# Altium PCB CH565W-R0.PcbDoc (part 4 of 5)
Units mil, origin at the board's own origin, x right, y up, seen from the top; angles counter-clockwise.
Board outline 3947.04 x 3947.04 mil, 4 copper layers (Top Layer, Layer 1, Layer 2, Bottom Layer), stack 23.756 mil thick; 204 components, 168 nets, 932 pads, 1005 vias.
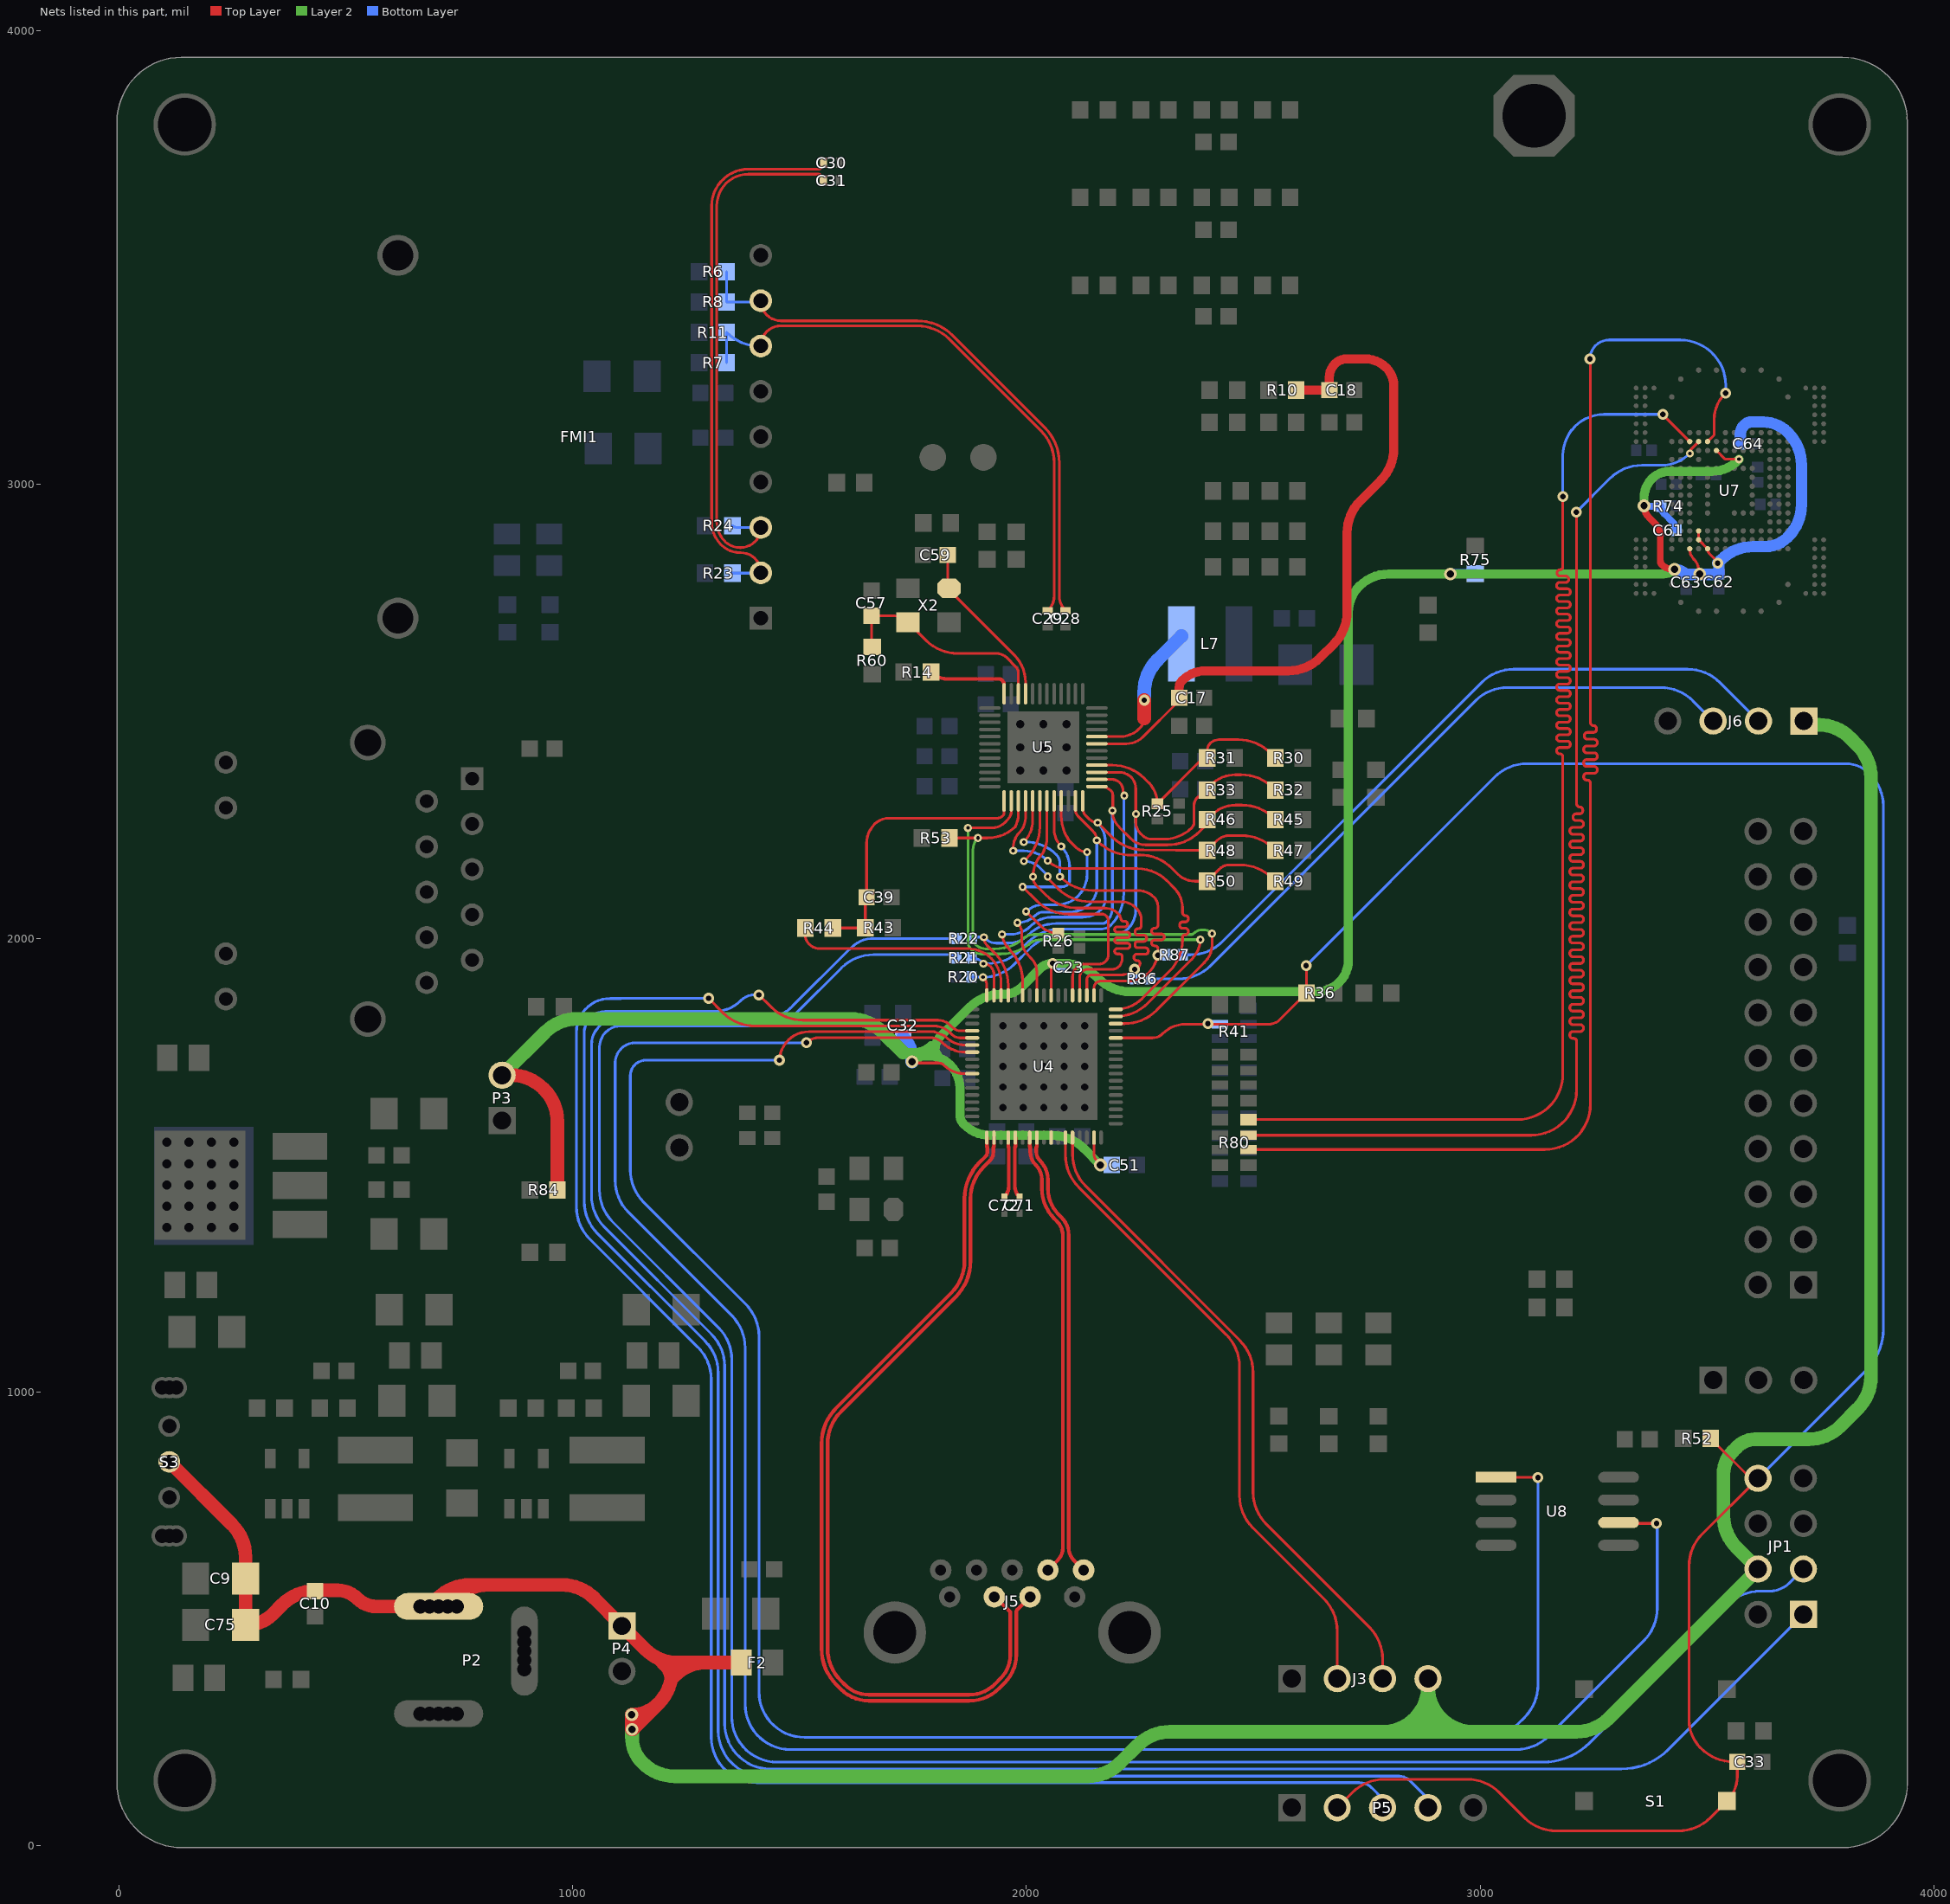
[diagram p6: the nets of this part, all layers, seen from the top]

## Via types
v1: diameter 17.72, hole 7.87, Top Layer to Bottom Layer, 556 vias
v2: diameter 24, hole 12, Top Layer to Bottom Layer, 366 vias
v3: diameter 28, hole 16, Top Layer to Bottom Layer, 63 vias
v4: diameter 17.72, hole 7.87, Top Layer to Bottom Layer, tented both sides, 8 vias
v5: diameter 24, hole 12, Top Layer to Bottom Layer, tented both sides, 5 vias
v6: diameter 26, hole 14, Top Layer to Bottom Layer, 2 vias
v7: diameter 19.68, hole 10, Top Layer to Bottom Layer, 1 vias
v8: diameter 20, hole 10, Top Layer to Bottom Layer, 1 vias
v9: diameter 28, hole 16, Top Layer to Bottom Layer, tented both sides, 1 vias
v10: diameter 32, hole 18, Top Layer to Bottom Layer, 1 vias
v11: diameter 17.72, hole 12, Top Layer to Bottom Layer, 1 vias

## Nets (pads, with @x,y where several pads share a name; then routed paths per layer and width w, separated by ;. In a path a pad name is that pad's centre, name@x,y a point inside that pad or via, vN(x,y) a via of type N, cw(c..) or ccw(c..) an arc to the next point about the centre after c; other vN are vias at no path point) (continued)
NetR80_6: R80.6 U7.J5 | length 3153.7
  Top Layer w6: R80.6@2489.51,1533.95 3143.25,1533.95 ccw(c3143.25,1633.95) 3243.25,1633.95 3243.25,2338.86 3243.25,2341.86 ccw(c3236.5,2341.86) 3236.5,2348.61 3235,2348.61 cw(c3235,2355.36) 3228.25,2355.36 3228.25,2356.86 cw(c3235,2356.86) 3235,2363.61 3251.5,2363.61 ccw(c3251.5,2370.36) 3258.25,2370.36 3258.25,2371.86 ccw(c3251.5,2371.86) 3251.5,2378.61 3235,2378.61 cw(c3235,2385.36) 3228.25,2385.36 3228.25,2386.86 cw(c3235,2386.86) 3235,2393.61 3251.5,2393.61 ccw(c3251.5,2400.36) 3258.25,2400.36 3258.25,2401.86 ccw(c3251.5,2401.86) 3251.5,2408.61 3235,2408.61 cw(c3235,2415.36) 3228.25,2415.36 3228.25,2416.86 cw(c3235,2416.86) 3235,2423.61 3251.5,2423.61 ccw(c3251.5,2430.36) 3258.25,2430.36 3258.25,2431.86 ccw(c3251.5,2431.86) 3251.5,2438.61 3236.56,2438.61 cw(c3236.56,2445.36) 3229.81,2445.36 3229.81,2446.86 cw(c3236.56,2446.86) 3236.56,2453.61 3250,2453.61 ccw(c3250,2460.36) 3256.75,2460.36 3256.75,2461.86 ccw(c3250,2461.86) 3250,2468.61 cw(c3250,2475.36) 3243.25,2475.36 3243.25,2543.86 3243.25,3275.62 ccw(c3242.12,3275.62) v2(3242.12,3276.76) ; U7.J5@3501.47,3094.85 3515.93,3109.33 3515.93,3143.38 cw(c3594.92,3143.38) 3539.07,3199.23 v2(3541.48,3201.64)
  Bottom Layer w6: v2(3242.12,3276.76) cw(c3284.22,3276.76) 3284.22,3318.85 3441.48,3318.85 cw(c3441.48,3218.85) 3541.48,3218.85 v2(3541.48,3201.64)
NetR80_7: R80.7 U7.J4 | length 3184.2
  Top Layer w6: R80.7@2489.51,1565.45 3112.82,1565.45 ccw(c3112.82,1665.45) 3212.82,1665.44 3212.82,1769.53 3212.82,1772.53 ccw(c3206.07,1772.53) 3206.07,1779.28 3204.57,1779.28 cw(c3204.57,1786.03) 3197.82,1786.03 3197.82,1787.53 cw(c3204.57,1787.53) 3204.57,1794.28 3221.07,1794.28 ccw(c3221.07,1801.03) 3227.82,1801.03 3227.82,1802.53 ccw(c3221.07,1802.53) 3221.07,1809.28 3204.57,1809.28 cw(c3204.57,1816.03) 3197.82,1816.03 3197.82,1817.53 cw(c3204.57,1817.53) 3204.57,1824.28 3221.07,1824.28 ccw(c3221.07,1831.03) 3227.82,1831.03 3227.82,1832.53 ccw(c3221.07,1832.53) 3221.07,1839.28 3204.57,1839.28 cw(c3204.57,1846.03) 3197.82,1846.03 3197.82,1847.53 cw(c3204.57,1847.53) 3204.57,1854.28 3221.07,1854.28 ccw(c3221.07,1861.03) 3227.82,1861.03 3227.82,1862.53 ccw(c3221.07,1862.53) 3221.07,1869.28 3204.57,1869.28 cw(c3204.57,1876.03) 3197.82,1876.03 3197.82,1877.53 cw(c3204.57,1877.53) 3204.57,1884.28 3221.07,1884.28 ccw(c3221.07,1891.03) 3227.82,1891.03 3227.82,1892.53 ccw(c3221.07,1892.53) 3221.07,1899.28 3204.57,1899.28 cw(c3204.57,1906.03) 3197.82,1906.03 3197.82,1907.53 cw(c3204.57,1907.53) 3204.57,1914.28 3221.07,1914.28 ccw(c3221.07,1921.03) 3227.82,1921.03 3227.82,1922.53 ccw(c3221.07,1922.53) 3221.07,1929.28 3204.57,1929.28 cw(c3204.57,1936.03) 3197.82,1936.03 3197.82,1937.53 cw(c3204.57,1937.53) 3204.57,1944.28 3221.07,1944.28 ccw(c3221.07,1951.03) 3227.82,1951.03 3227.82,1952.53 ccw(c3221.07,1952.53) 3221.07,1959.28 3204.57,1959.28 cw(c3204.57,1966.03) 3197.82,1966.03 3197.82,1967.53 cw(c3204.57,1967.53) 3204.57,1974.28 3221.07,1974.28 ccw(c3221.07,1981.03) 3227.82,1981.03 3227.82,1982.53 ccw(c3221.07,1982.53) 3221.07,1989.28 3204.57,1989.28 cw(c3204.57,1996.03) 3197.82,1996.03 3197.82,1997.53 cw(c3204.57,1997.53) 3204.57,2004.28 3221.07,2004.28 ccw(c3221.07,2011.03) 3227.82,2011.03 3227.82,2012.53 ccw(c3221.07,2012.53) 3221.07,2019.28 3204.57,2019.28 cw(c3204.57,2026.03) 3197.82,2026.03 3197.82,2027.53 cw(c3204.57,2027.53) 3204.57,2034.28 3221.07,2034.28 ccw(c3221.07,2041.03) 3227.82,2041.03 3227.82,2042.53 ccw(c3221.07,2042.53) 3221.07,2049.28 3204.57,2049.28 cw(c3204.57,2056.03) 3197.82,2056.03 3197.82,2057.53 cw(c3204.57,2057.53) 3204.57,2064.28 3221.07,2064.28 ccw(c3221.07,2071.03) 3227.82,2071.03 3227.82,2072.53 ccw(c3221.07,2072.53) 3221.07,2079.28 3204.57,2079.28 cw(c3204.57,2086.03) 3197.82,2086.03 3197.82,2087.53 cw(c3204.57,2087.53) 3204.57,2094.28 3221.07,2094.28 ccw(c3221.07,2101.03) 3227.82,2101.03 3227.82,2102.53 ccw(c3221.07,2102.53) 3221.07,2109.28 3204.57,2109.28 cw(c3204.57,2116.03) 3197.82,2116.03 3197.82,2117.53 cw(c3204.57,2117.53) 3204.57,2124.28 3221.07,2124.28 ccw(c3221.07,2131.03) 3227.82,2131.03 3227.82,2132.53 ccw(c3221.07,2132.53) 3221.07,2139.28 3204.57,2139.28 cw(c3204.57,2146.03) 3197.82,2146.03 3197.82,2147.53 cw(c3204.57,2147.53) 3204.57,2154.28 3221.07,2154.28 ccw(c3221.07,2161.03) 3227.82,2161.03 3227.82,2162.53 ccw(c3221.07,2162.53) 3221.07,2169.28 3204.57,2169.28 cw(c3204.57,2176.03) 3197.82,2176.03 3197.82,2177.53 cw(c3204.57,2177.53) 3204.57,2184.28 3221.07,2184.28 ccw(c3221.07,2191.03) 3227.82,2191.03 3227.82,2192.53 ccw(c3221.07,2192.53) 3221.07,2199.28 3204.57,2199.28 cw(c3204.57,2206.03) 3197.82,2206.03 3197.82,2207.53 cw(c3204.57,2207.53) 3204.57,2214.28 3221.07,2214.28 ccw(c3221.07,2221.03) 3227.82,2221.03 3227.82,2222.53 ccw(c3221.07,2222.53) 3221.07,2229.28 3204.57,2229.28 cw(c3204.57,2236.03) 3197.82,2236.03 3197.82,2237.53 cw(c3204.57,2237.53) 3204.57,2244.28 3221.07,2244.28 ccw(c3221.07,2251.03) 3227.82,2251.03 3227.82,2252.53 ccw(c3221.07,2252.53) 3221.07,2259.28 3211.72,2259.28 cw(c3211.72,2266.03) 3204.97,2266.03 3204.97,2267.53 cw(c3211.72,2267.53) 3211.72,2274.28 3219.57,2274.28 ccw(c3219.57,2281.03) 3226.32,2281.03 3226.32,2282.53 ccw(c3219.57,2282.53) 3219.57,2289.28 cw(c3219.57,2296.03) 3212.82,2296.03 3212.82,2345.59 3212.82,2348.59 v2@3212.82,2939.27 ; v4(3462.46,3068.75) 3464.7,3070.99 3464.7,3077.76 U7.J4@3481.78,3094.85
  Bottom Layer w6: v2(3211.9,2939.27) 3285.85,3013.21 cw(c3356.56,2942.5) 3356.56,3042.5 3399.09,3042.5 ccw(c3399.09,3132.11) v4(3462.46,3068.75)
NetR80_8: R80.8 U7.J3 | length 3166.7
  Top Layer w6: R80.8@2489.51,1600.1 3082.41,1600.1 ccw(c3082.41,1700.1) 3182.41,1700.1 3182.41,2397 3182.41,2400 ccw(c3176.11,2400) 3176.11,2406.3 3175.12,2406.3 cw(c3175.12,2412.6) 3168.82,2412.6 3168.82,2414 cw(c3175.12,2414) 3175.12,2420.3 3192.52,2420.3 ccw(c3192.52,2426.6) 3198.82,2426.6 3198.82,2428 ccw(c3192.52,2428) 3192.52,2434.3 3175.12,2434.3 cw(c3175.12,2440.6) 3168.82,2440.6 3168.82,2442 cw(c3175.12,2442) 3175.12,2448.3 3192.52,2448.3 ccw(c3192.52,2454.6) 3198.82,2454.6 3198.82,2456 ccw(c3192.52,2456) 3192.52,2462.3 3175.12,2462.3 cw(c3175.12,2468.6) 3168.82,2468.6 3168.82,2470 cw(c3175.12,2470) 3175.12,2476.3 3192.52,2476.3 ccw(c3192.52,2482.6) 3198.82,2482.6 3198.82,2484 ccw(c3192.52,2484) 3192.52,2490.3 3175.12,2490.3 cw(c3175.12,2496.6) 3168.82,2496.6 3168.82,2498 cw(c3175.12,2498) 3175.12,2504.3 3192.52,2504.3 ccw(c3192.52,2510.6) 3198.82,2510.6 3198.82,2512 ccw(c3192.52,2512) 3192.52,2518.3 3175.12,2518.3 cw(c3175.12,2524.6) 3168.82,2524.6 3168.82,2526 cw(c3175.12,2526) 3175.12,2532.3 3192.52,2532.3 ccw(c3192.52,2538.6) 3198.82,2538.6 3198.82,2540 ccw(c3192.52,2540) 3192.52,2546.3 3175.12,2546.3 cw(c3175.12,2552.6) 3168.82,2552.6 3168.82,2554 cw(c3175.12,2554) 3175.12,2560.3 3192.52,2560.3 ccw(c3192.52,2566.6) 3198.82,2566.6 3198.82,2568 ccw(c3192.52,2568) 3192.52,2574.3 3175.12,2574.3 cw(c3175.12,2580.6) 3168.82,2580.6 3168.82,2582 cw(c3175.12,2582) 3175.12,2588.3 3192.52,2588.3 ccw(c3192.52,2594.6) 3198.82,2594.6 3198.82,2596 ccw(c3192.52,2596) 3192.52,2602.3 3175.12,2602.3 cw(c3175.12,2608.6) 3168.82,2608.6 3168.82,2610 cw(c3175.12,2610) 3175.12,2616.3 3192.52,2616.3 ccw(c3192.52,2622.6) 3198.82,2622.6 3198.82,2624 ccw(c3192.52,2624) 3192.52,2630.3 3175.12,2630.3 cw(c3175.12,2636.6) 3168.82,2636.6 3168.82,2638 cw(c3175.12,2638) 3175.12,2644.3 3192.52,2644.3 ccw(c3192.52,2650.6) 3198.82,2650.6 3198.82,2652 ccw(c3192.52,2652) 3192.52,2658.3 3175.12,2658.3 cw(c3175.12,2664.6) 3168.82,2664.6 3168.82,2666 cw(c3175.12,2666) 3175.12,2672.3 3192.52,2672.3 ccw(c3192.52,2678.6) 3198.82,2678.6 3198.82,2680 ccw(c3192.52,2680) 3192.52,2686.3 3175.12,2686.3 cw(c3175.12,2692.6) 3168.82,2692.6 3168.82,2694 cw(c3175.12,2694) 3175.12,2700.3 3192.52,2700.3 ccw(c3192.52,2706.6) 3198.82,2706.6 3198.82,2708 ccw(c3192.52,2708) 3192.52,2714.3 3175.12,2714.3 cw(c3175.12,2720.6) 3168.82,2720.6 3168.82,2722 cw(c3175.12,2722) 3175.12,2728.3 3192.52,2728.3 ccw(c3192.52,2734.6) 3198.82,2734.6 3198.82,2736 ccw(c3192.52,2736) 3192.52,2742.3 3175.12,2742.3 cw(c3175.12,2748.6) 3168.82,2748.6 3168.82,2750 cw(c3175.12,2750) 3175.12,2756.3 3192.52,2756.3 ccw(c3192.52,2762.6) 3198.82,2762.6 3198.82,2764 ccw(c3192.52,2764) 3192.52,2770.3 3175.12,2770.3 cw(c3175.12,2776.6) 3168.82,2776.6 3168.82,2778 cw(c3175.12,2778) 3175.12,2784.3 3188.9,2784.3 ccw(c3188.9,2790.6) 3195.2,2790.6 3195.2,2792 ccw(c3188.9,2792) 3188.9,2798.3 3176.11,2798.3 cw(c3176.11,2804.6) 3169.81,2804.6 3169.81,2806 cw(c3176.11,2806) 3176.11,2812.3 ccw(c3176.11,2818.6) 3182.41,2818.6 3182.41,2937.19 v2(3182.41,2973.49) ; v2(3402.8,3154.97) 3402.8,3154.16 U7.J3@3462.1,3094.85
  Bottom Layer w6: v2(3182.41,2973.49) 3182.41,3064.16 cw(c3273.22,3064.16) 3273.22,3154.97 v2(3402.8,3154.97)
PA19: U4.10
PB24: R44.2 U4.49 | length 535
  Top Layer w6: R44.2@1512.38,2022.43 1512.38,2007.08 ccw(c1540.98,2007.08) 1520.75,1986.86 ccw(c1544.85,2010.95) 1544.85,1976.88 1870.85,1976.88 cw(c1870.85,1904.71) 1921.89,1955.74 cw(c1868.24,1902.09) 1944.11,1902.09 U4.49@1944.11,1873.9
PHYRSTB: C39.2 R43.1 R44.1 U5.13 | length 621.3
  Top Layer w6: R44.1@1573.01,2022.43 1642.99,2022.43 ccw(c1642.99,2024.94) R43.1@1644.77,2023.17 1644.77,2083.54 cw(c1654.35,2083.54) C39.2@1647.57,2090.31 1647.57,2189.92 1647.57,2209.43 cw(c1706.65,2209.43) 1664.88,2251.21 cw(c1697.2,2218.88) 1697.2,2264.59 1745.25,2264.59 1935.08,2264.59 ccw(c1935.08,2282.62) 1947.83,2269.87 ccw(c1941.09,2276.61) 1950.62,2276.61 U5.13@1950.62,2297.13
PWR: C9.2 C10.2 C75.2 F2.2 J3.4 J6.1 JP1.4 P2.1 P4.1 S3.1 | length 7815.1
  Top Layer w30: S3.1@110.18,845.58 249.02,706.74 cw(c178.31,636.03) 278.31,636.03 C9.2@278.31,588.13 C75.2@278.31,486.14 282.16,486.14 ccw(c282.16,564.49) 337.56,509.09 359.63,531.15 cw(c430.34,460.44) 430.34,560.44 C10.2@431.73,560.44 ; C10.2@431.73,562.32 481.16,562.32 cw(c481.16,500.89) 524.6,544.33 ccw(c567.23,586.96) 567.23,526.67 P2.1@664.07,526.67 P2.1@684.07,526.67 ; P2.1@684.07,540.95 P2.1@684.07,526.67 ; P2.1@704.07,526.67 722.44,545.04 cw(c793.15,474.33) 793.15,574.33 ; P2.1@724.07,526.67 742.44,545.04 cw(c813.15,474.33) 813.15,574.33 ; 1187.97,311.98 1188.86,312.87 ccw(c1118.15,383.58) 1216.67,366.44 ; F2.2@1371.15,402.99 1294.64,402.99 ; P2.1@684.07,526.67 702.44,545.04 cw(c773.15,474.33) 773.15,574.33 793.15,574.33 ; 793.15,574.33 813.15,574.33 ; 813.15,574.33 976.1,574.33 cw(c976.1,474.33) 1046.81,545.04 P4.1@1108.22,483.63 1159.57,432.28 ccw(c1230.28,502.99) 1189.19,411.82 ; 1189.19,411.82 ccw(c1230.28,502.99) 1230.28,402.99 1237.56,402.99 ; 1189.19,411.82 1204.02,396.99 cw(c1173.47,366.44) 1216.67,366.44 ; 1216.67,366.44 ccw(c1118.15,383.58) 1218.15,383.58 cw(c1237.56,383.58) 1237.56,402.99 ; 1216.67,366.44 1223.93,373.7 cw(c1294.64,302.99) 1294.64,402.99 ; 1237.56,402.99 1294.64,402.99 ; v3(1129.84,287.9) ccw(c1129.84,370.1) 1187.94,311.95 1132.76,256.77 cw(c1130.21,259.32) v3(1130.21,255.71) 1130.21,287.54 v3(1129.84,287.9)
  Layer 2 w30: v3(1129.84,287.9) cw(c1126.07,284.13) 1131.41,284.13 1131.41,224.96 ; v3(1130.21,255.71) 1130.21,238.8 ccw(c1210.53,238.8) 1131.41,224.96 ; J3.4@2885.09,367.45 J3.4@2885.09,350.37 ; J6.1@3713.66,2478.72 3713.66,2470.27 3747,2470.27 cw(c3747,2373.81) 3815.2,2442.02 3832.46,2424.76 cw(c3761.75,2354.05) 3861.75,2354.05 3861.75,1033.06 cw(c3761.75,1033.06) 3832.46,962.35 3794.57,924.46 cw(c3723.86,995.17) 3723.86,895.17 3606.65,895.17 ccw(c3606.65,839.43) 3567.23,878.85 3557.83,869.44 ccw(c3608.84,818.44) 3536.7,818.44 3536.7,726.61 ccw(c3636.7,726.61) 3565.99,655.9 JP1.4@3612.66,609.23 3283.09,279.66 cw(c3212.38,350.37) 3212.38,250.37 2985.09,250.37 ; 1131.41,224.96 ccw(c1210.53,238.8) 1153.73,182 1154.11,181.62 ccw(c1224.82,252.33) 1224.82,152.33 2135.56,152.33 ccw(c2135.56,252.33) 2206.27,181.62 2245.73,221.08 cw(c2316.44,150.37) 2316.44,250.37 2785.09,250.37 ; 2785.09,250.37 ccw(c2785.09,350.37) J3.4@2885.09,350.37 ; 2785.09,250.37 2853.49,250.37 ; 2853.49,250.37 ccw(c2853.49,281.96) 2885.09,281.96 2885.09,299.15 ; 2853.49,250.37 2933.87,250.37 ; 2885.09,299.15 ccw(c2933.87,299.15) 2933.87,250.37 ; 2885.09,299.15 J3.4@2885.09,350.37 ; J3.4@2885.09,350.37 ccw(c2985.09,350.37) 2985.09,250.37 ; 2933.87,250.37 2985.09,250.37
REGOUT: L7.1 U5.32 | length 362
  Top Layer w6: U5.32@2155.35,2444.41 2206.47,2444.41 ccw(c2206.47,2504.19) 2248.74,2461.92 ccw(c2204.49,2506.17) 2267.07,2506.17 2267.07,2509.74
  Top Layer w30: 2259.69,2484.21 v2(2259.69,2524.71)
  Bottom Layer w30: v2(2259.69,2524.71) 2259.69,2542.66 cw(c2359.69,2542.66) 2288.98,2613.37 L7.1@2341.44,2665.83
RGMII_MDC: U4.33 U5.14 | length 1207.3
  Top Layer w6: v1(1871,2243) 1924.08,2243 1924.37,2243.29 ccw(c1924.37,2281.73) 1951.55,2254.55 ; 1951.56,2254.57 1959.29,2262.29 ; 1959.3,2262.3 ccw(c1942.19,2279.39) 1962.44,2266.18 ccw(c1942.19,2279.39) 1966.37,2279.39 U5.14@1966.37,2302.68 ; U4.33@2196.78,1827.36 ccw(c2196.78,1927) 2267.23,1856.54 2363.6,1952.91 ccw(c2314.1,2002.42) v1@2384.11,2002.42
  Layer 2 w6: v1(1871,2243) 1871,1993.43 ccw(c1899,1993.43) 1879.2,1973.63 ccw(c1899.3,1993.73) 1899.29,1965.3 1944,1965.3 ccw(c1944,2065.3) 2004.21,1985.46 ; v1(2383.28,1996.84) 2386.18,1993.94 ccw(c2379.17,1986.92) 2379.17,1996.84 2031.69,1996.84 ccw(c2031.69,1957.98) 2010.24,1990.39 ; 2004.21,1985.46 ccw(c1944,2065.3) 2010.24,1990.39 ; 2004.21,1985.46 cw(c2031.69,1957.98) 2010.24,1990.39
RGMII_MDIO: R53.2 U4.32 U5.15 | length 1306.6
  Top Layer w6: R53.2@1830.07,2220.81 1914.42,2220.81 ccw(c1914.42,2307.37) 1975.63,2246.16 ccw(c1920.26,2273.74) 1982.12,2273.74 U5.15@1982.12,2302.68 ; U4.32@2196.78,1811.61 2216.3,1811.61 ccw(c2216.3,1911.61) 2287.01,1840.9 2387.37,1941.26 ccw(c2316.66,2011.97) 2394.78,1949.54 ccw(c2360.44,1983.87) 2405.96,1966.95 ccw(c2360.44,1983.87) 2409,1983.87 v1(2409,2010)
  Layer 2 w6: v1(1893,2221) ccw(c1919.56,2194.44) 1882,2194.44 1882,2001.36 ccw(c1904.69,2001.36) 1888.64,1985.32 ccw(c1909.84,2006.52) 1909.84,1976.54 1930.17,1976.54 ccw(c1930.17,2076.54) 1996.78,2001.96 ; 1992.54,1998.37 cw(c2015.88,1975.03) 1996.78,2001.96 ; v1(2409,2010) ccw(c2386.59,1987.59) 2393.97,2018.41 2388.01,2018.41 ccw(c2388.01,1990.69) 2368.41,2010.29 cw(c2362.98,2015.73) 2362.98,2008.04 2015.88,2008.04 ccw(c2015.88,1975.03) 1996.78,2001.96
RGMII_RXC: R25.2 R30.2 R31.1 U5.28 | length 519.8
  Top Layer w6: U5.28@2155.35,2381.42 2189.52,2381.42 cw(c2189.52,2281.42) 2260.23,2352.13 2269.2,2343.16 cw(c2222.61,2296.57) R25.2@2288.5,2296.57 2383.21,2391.28 cw(c2398.43,2376.05) R31.1@2398.43,2397.59 2398.43,2413.55 cw(c2421.43,2413.55) 2405.17,2429.81 cw(c2424.04,2410.94) 2424.04,2437.62 2467.13,2437.62 cw(c2467.13,2337.62) 2537.84,2408.33 R30.2@2548.59,2397.59
RGMII_RXD0: R21.1 U4.50 U5.26 | length 795.6
  Top Layer w6: v1(1905.2,1943.91) cw(c1905.2,1921.68) 1920.92,1937.4 cw(c1902.98,1919.46) 1928.36,1919.46 U4.50@1928.36,1873.9 ; U5.26@2155.35,2349.93 2188.26,2349.93 cw(c2188.26,2324.79) 2206.04,2342.56 cw(c2190.38,2326.91) 2212.52,2326.91 v1@2212.52,2314.19
  Bottom Layer w6: R21.1@1878.52,1957.02 cw(c1878.52,1924.24) 1901.7,1947.42 v1(1905.2,1943.91) 1914.97,1943.91 ccw(c1914.97,2043.91) 1985.68,1973.2 2003.59,1991.11 cw(c2074.3,1920.4) 2074.3,2020.4 2166.88,2020.4 ccw(c2166.88,2046.35) 2185.23,2028 ccw(c2114.52,2098.71) 2214.52,2098.71 v1@2214.52,2314.19
  other v1: 2215.52,2314.19
RGMII_RXD1: R22.1 R45.2 R46.1 U4.48 U5.25 | length 1223.9
  Top Layer w6: v1(1905.97,2002.04) ccw(c1932.45,2002.04) 1913.73,1983.32 1930.56,1966.48 cw(c1859.85,1895.77) 1959.85,1895.77 U4.48@1959.85,1873.9 ; U5.25@2155.35,2334.18 2163.85,2334.18 cw(c2163.85,2301.73) 2186.8,2324.67 cw(c2178.22,2316.1) 2190.35,2316.1 v1@2190.35,2281.15 ; v1(2189.35,2281.15) ccw(c2240.43,2281.15) 2204.31,2245.04 2230.69,2218.67 ccw(c2262.13,2250.11) 2262.13,2205.64 2311.08,2205.64 ccw(c2311.08,2305.64) 2381.79,2234.93 2398.43,2251.58 cw(c2403.74,2251.58) R46.1@2399.98,2255.32 ; R46.1@2398.43,2261.58 2408.7,2271.85 cw(c2460.89,2219.66) 2460.89,2293.46 2475.28,2293.46 cw(c2475.28,2193.46) 2545.99,2264.17 R45.2@2548.59,2261.58 ; R45.2@2548.37,2251.79 R45.2@2548.59,2251.58
  Bottom Layer w6: R22.1@1879.11,1999.15 cw(c1887.36,1990.89) 1887.36,2002.57 1905.97,2002.57 1909.7,1998.84 ccw(c1933.3,2022.44) 1933.3,1989.06 1960.74,1989.06 ccw(c1960.74,2049.37) 2003.38,2006.73 cw(c2065.25,1944.86) 2065.25,2032.36 2167.01,2032.36 ccw(c2167.01,2046.23) 2176.81,2036.42 ccw(c2146.54,2066.69) 2189.35,2066.69 v1(2189.35,2281.15)
RGMII_RXD2: R47.2 R48.1 U4.46 U5.24 | length 1081
  Top Layer w6: v1(1946.21,2008.38) ccw(c2001.06,2014.78) 1962.02,1975.74 cw(c1957.77,1971.51) 1963.2,1974.06 cw(c1895.23,1906.1) 1991.35,1906.1 U4.46@1991.35,1873.9 ; U5.24@2123.85,2302.68 2123.85,2286.6 ccw(c2146.35,2286.6) 2125.74,2277.56 ccw(c2146.35,2286.6) 2130.44,2270.69 2138.9,2262.23 ccw(c2156.99,2280.32) v1(2156.99,2254.74) 2187.8,2223.93 ccw(c2258.51,2294.64) 2189.72,2222.06 ccw(c2258.51,2294.64) 2258.51,2194.64 cw(c2258.51,2188.64) 2258.6,2194.64 2398.43,2193.18 R48.1@2398.48,2193.17 ; R48.1@2398.43,2188.57 R48.1@2400.93,2191.07 ; R48.1@2398.43,2193.57 2419.69,2214.83 cw(c2447.24,2187.28) 2447.24,2226.24 2474.49,2226.24 cw(c2474.49,2126.24) 2545.2,2196.95 R47.2@2548.59,2193.57 ; R47.2@2548.45,2188.71 R47.2@2548.59,2188.57
  Bottom Layer w6: v1(1946.21,2008.38) 1963.48,2008.38 ccw(c1963.48,2075.18) 2010.71,2027.95 cw(c2054.88,1983.78) 2054.88,2046.24 2123.69,2046.24 ccw(c2123.69,2104.35) 2164.77,2063.26 ccw(c2143.93,2084.11) 2173.41,2084.11 2173.41,2215.1 ccw(c2117.35,2215.1) 2170.67,2232.4 ccw(c2117.35,2215.1) v1(2156.99,2254.74)
RGMII_RXD3: R49.2 R50.1 U4.44 U5.23 | length 1039.2
  Top Layer w6: v1(1980.11,2034.15) cw(c1956.73,2010.77) 1989.79,2010.77 1989.79,1994.93 ccw(c2034.68,1994.93) 2002.94,1963.18 2010.28,1955.84 ; 2010.31,1955.81 cw(c1979.95,1925.51) 2022.85,1925.51 U4.44@2022.85,1873.9 ; U5.23@2108.1,2302.68 2108.1,2283.07 ccw(c2128.79,2283.07) 2114.16,2268.45 2146.73,2235.88 cw(c2126.67,2215.82) 2155.04,2215.82 2158.5,2212.35 ccw(c2229.21,2283.06) 2216.03,2183.93 ccw(c2229.21,2283.06) 2229.21,2183.06 2249.83,2183.06 ; 2249.83,2183.67 cw(c2249.83,2083.67) 2320.54,2154.38 2333.88,2141.05 ccw(c2371.26,2178.44) 2371.26,2125.57 R50.1@2398.43,2125.57 ; R50.1@2399.78,2126.12 ccw(c2399.78,2124.22) R50.1@2398.43,2125.57 ; R49.2@2534.74,2127.17 cw(c2531.62,2122.04) R49.2@2535.79,2126.36 ; R49.2@2548.59,2125.57 2541.95,2132.2 ccw(c2471.24,2061.49) 2471.24,2161.49 2447.02,2161.49 ccw(c2447.02,2130.92) 2425.4,2152.54 R50.1@2398.43,2125.57
  Bottom Layer w6: v1(1980.11,2034.15) ccw(c1980.11,2091.39) 2020.58,2050.91 cw(c2036.32,2035.17) 2036.32,2057.43 2094.78,2057.43 ccw(c2094.78,2121.85) 2140.33,2076.3 ccw(c2104.82,2111.81) 2155.04,2111.81 v1(2155.04,2215.81)
RGMII_RXDV: R20.1 R32.2 R33.1 U4.51 U5.27 | length 1274.3
  Top Layer w6: v1(1904.17,1913.87) v1@1906.35,1911.69 ; v1@1906.36,1911.68 cw(c1891.23,1896.58) 1912.61,1896.58 U4.51@1912.61,1873.9 ; U5.27@2155.35,2365.67 2205.11,2365.67 cw(c2205.11,2330.04) 2230.31,2355.24 cw(c2204.41,2329.35) 2241.03,2329.35 2241.03,2255.21 ccw(c2274.2,2255.21) 2241.07,2253.52 ccw(c2274.2,2255.21) 2250.75,2231.76 2255.66,2226.84 ccw(c2276.33,2247.51) 2276.33,2218.28 2303.29,2218.28 ccw(c2303.29,2305.2) 2364.76,2243.74 ccw(c2353.42,2255.08) 2369.45,2255.08 2369.45,2292.92 cw(c2392.89,2292.92) 2376.32,2309.5 cw(c2388.59,2297.22) 2388.59,2314.58 ccw(c2388.59,2326.98) R33.1@2397.36,2318.21 ; R33.1@2398.43,2329.58 2407.07,2338.22 cw(c2460.47,2284.81) 2412.17,2342.87 cw(c2460.47,2284.81) 2439.18,2357.27 cw(c2460.47,2284.81) 2460.47,2360.34 2473.41,2360.34 cw(c2473.41,2260.34) 2544.12,2331.05 R32.2@2548.59,2326.58
  Bottom Layer w6: R20.1@1878.26,1914.38 1902.93,1914.38 cw(c1902.93,1912.63) v1(1904.17,1913.87) ccw(c1904.17,2011.04) 1972.88,1942.33 2009.71,1979.15 cw(c2080.42,1908.44) 2080.42,2008.44 2194.57,2008.44 ccw(c2194.57,2049.8) 2223.82,2020.55 ccw(c2182.26,2062.11) 2241.03,2062.11 v1@2241.03,2274.73
  other v1: 2241.27,2273.78
RGMII_TXC: R26.1 U5.21 | length 454.9
  Top Layer w6: v1(1999,2059) 2030.93,2027.07 ccw(c2070.34,2066.47) R26.1@2070.34,2010.74 ; U5.21@2076.61,2302.68 2076.61,2271.32 ccw(c2175.85,2271.32) 2093.76,2215.54 2109.38,2199.92 ccw(c2133.68,2224.22) v1(2133.68,2189.86)
  Bottom Layer w6: v1(1999,2059) 2001.14,2059 2002.6,2060.47 cw(c2033.9,2029.17) 2033.9,2073.43 2066.42,2073.43 ccw(c2066.42,2140.5) 2067.99,2073.45 ccw(c2066.42,2140.5) 2113.84,2093.07 ccw(c2065.96,2140.96) 2123.95,2106 ccw(c2065.96,2140.96) 2133.68,2140.96 v1(2133.68,2189.86)
RGMII_TXD0: U4.38 U5.19 | length 814.7
  Top Layer w6: U5.19@2045.11,2302.68 2045.11,2221.89 cw(c1976.86,2221.89) 2035.06,2186.24 ccw(c2085,2136.31) 2024.92,2173.43 ccw(c2085,2136.31) 2014.38,2136.31 v1(2014.38,2135.57) ccw(c2044.14,2135.57) 2023.1,2114.53 2042.03,2095.59 ccw(c2112.74,2166.31) 2104.85,2066.62 ccw(c2112.74,2166.31) 2112.74,2066.31 2171.45,2066.31 cw(c2171.45,2021.65) 2199.12,2056.7 cw(c2171.45,2021.65) 2202.55,2053.7 2203.03,2053.23 2205.63,2050.23 2208.63,2041.22 ccw(c2214.32,2043.12) 2214.32,2037.12 2216.97,2037.12 cw(c2216.97,2031.12) 2216.97,2025.12 2200.23,2025.12 ccw(c2200.23,2019.12) 2200.23,2013.12 2222.23,2013.12 cw(c2222.23,2007.12) 2222.23,2001.12 2200.23,2001.12 ccw(c2200.23,1995.12) 2200.23,1989.12 2222.23,1989.12 cw(c2222.23,1983.12) 2222.23,1977.12 2200.23,1977.12 ccw(c2200.23,1971.12) 2200.23,1965.12 2205.23,1965.12 cw(c2205.23,1959.12) 2211.23,1959.12 2211.23,1956.12 cw(c2184.69,1956.12) 2203.46,1937.35 cw(c2189.47,1951.34) 2189.47,1931.55 2134.43,1931.55 ccw(c2134.43,1914.46) 2117.33,1914.46 U4.38@2117.33,1873.9
RGMII_TXD1: R86.2 U4.37 U5.18 | length 844.9
  Top Layer w6: v1@1997.88,2172.71 2000.07,2174.9 ccw(c1929.36,2245.61) 2029.36,2245.61 U5.18@2029.36,2302.68 ; v1(2047,2136) 2047,2131.8 2069.14,2109.66 ccw(c2139.85,2180.37) 2102.62,2087.56 ccw(c2139.85,2180.37) 2139.85,2080.37 2209.91,2080.37 cw(c2209.91,2037.36) 2240.32,2067.77 2243.48,2064.61 cw(c2220.67,2041.8) 2252.93,2041.8 2252.93,2027.05 cw(c2246.63,2027.05) 2246.63,2020.75 2245.64,2020.75 ccw(c2245.64,2014.45) 2239.34,2014.45 2239.34,2013.05 ccw(c2245.64,2013.05) 2245.64,2006.75 2258.53,2006.75 cw(c2258.53,2000.45) 2264.83,2000.45 2264.83,1999.05 cw(c2258.53,1999.05) 2258.53,1992.75 2245.53,1992.75 ccw(c2245.53,1986.45) 2239.23,1986.45 2239.23,1985.05 ccw(c2245.53,1985.05) 2245.53,1978.75 2262.18,1978.75 cw(c2262.18,1972.45) 2268.48,1972.45 2268.48,1971.05 cw(c2262.18,1971.05) 2262.18,1964.75 2243.23,1964.75 ccw(c2243.23,1958.45) 2236.93,1958.45 2236.93,1957.05 ccw(c2243.23,1957.05) 2243.23,1950.75 2244.22,1950.75 cw(c2244.22,1944.45) 2250.33,1942.92 2249.92,1941.3 cw(c2227.46,1953.31) v2@2248.04,1938.3 ; U4.37@2133.08,1873.9 2133.08,1908.63 cw(c2143.36,1908.63) 2143.36,1918.91 2205.9,1918.91 ccw(c2205.9,1974.87) v2@2245.47,1935.3
  Bottom Layer w6: v1(1994.23,2169.79) cw(c1994.23,2119.75) 2029.61,2155.13 2045.77,2138.98 cw(c2042.79,2136) v1(2047,2136) ; R86.2@2237.41,1908.43 ccw(c2233.78,1912.06) R86.2@2238.91,1912.06 ; R86.2@2238.41,1910.43 2238.41,1931.24 v2(2238.47,1931.3)
RGMII_TXD2: R87.2 U4.36 U5.17 | length 832
  Top Layer w6: v1(1994,2212) ccw(c1946.65,2259.35) 2011.1,2241.16 ccw(c1946.65,2259.35) 2013.61,2259.35 U5.17@2013.61,2302.68 ; v1(2073.85,2135.56) 2074.86,2134.55 ccw(c2145.57,2205.26) 2106.6,2113.16 ccw(c2145.57,2205.26) 2145.57,2105.26 2244.54,2105.26 cw(c2244.54,2052.92) 2281.55,2089.93 cw(c2261.58,2069.95) 2288.68,2077.93 cw(c2261.58,2069.95) 2289.39,2074.93 2289.83,2069.95 2289.83,2028.65 cw(c2283.33,2028.65) 2283.33,2022.15 2282.33,2022.15 ccw(c2282.33,2015.65) 2282.33,2009.15 2297.33,2009.15 cw(c2297.33,2002.65) 2297.33,1996.15 2282.33,1996.15 ccw(c2282.33,1989.65) 2282.33,1983.15 2283.33,1983.15 cw(c2283.33,1976.65) 2289.83,1976.65 2289.83,1973.65 cw(c2218.94,1973.65) 2269.07,1923.53 cw(c2225.05,1967.55) 2225.05,1905.3 2163.44,1905.3 ccw(c2163.44,1890.69) 2148.83,1890.69 U4.36@2148.83,1873.9
  Bottom Layer w6: v1(1994,2212) 1999.49,2212 cw(c1999.49,2119.28) 2015.93,2210.53 cw(c1999.49,2119.28) 2065.05,2184.84 cw(c2043.81,2163.6) 2073.85,2163.6 v1(2073.85,2135.56)
  other v2: 2289.77,1962.47
RGMII_TXD3: U4.34 U5.16 | length 883.7
  Top Layer w6: v1(1970.69,2192.57) 1970.69,2199.91 cw(c2017.46,2199.91) 1984.39,2232.98 ccw(c1951.85,2265.52) 1997.87,2265.52 U5.16@1997.87,2302.68 ; v1(2046.96,2170.77) ccw(c2088.81,2212.62) 2088.81,2153.43 2245.15,2153.43 cw(c2245.15,2062.58) 2309.39,2126.82 2325.85,2110.36 cw(c2281.96,2066.47) 2344.03,2066.47 2344.03,2056.09 ccw(c2350.33,2056.09) 2350.33,2049.79 cw(c2350.33,2043.49) 2356.63,2043.49 2356.63,2042.09 cw(c2350.33,2042.09) 2350.33,2035.79 2344.03,2035.79 ccw(c2344.03,2029.49) 2337.73,2029.49 2337.73,2028.09 ccw(c2344.03,2028.09) 2344.03,2021.79 2350.33,2021.79 cw(c2350.33,2015.49) 2356.63,2015.49 2356.63,2014.09 cw(c2350.33,2014.09) 2350.33,2007.79 ccw(c2350.33,2001.49) 2344.03,2001.49 2344.03,1997.4 2343.18,1984.34 cw(c2244.03,1997.4) 2342.73,1981.34 cw(c2244.03,1997.4) 2314.74,1926.69 2255.47,1867.42 cw(c2196.78,1926.12) U4.34@2196.78,1843.11
  Bottom Layer w6: v1(1970.69,2192.57) 1994.33,2192.57 cw(c1994.33,2118.14) v1(2046.96,2170.77)
RGMII_TXEN: U4.39 U5.20 | length 736.2
  Top Layer w6: v1(1991.54,2113.09) 2022.22,2082.4 ccw(c2092.93,2153.12) 2092.93,2053.12 2166.06,2053.12 cw(c2166.06,2038.67) 2180.5,2038.67 2180.5,1963.46 cw(c2160.01,1963.46) 2160.01,1942.96 2130.03,1942.96 ccw(c2130.03,1914.51) 2109.93,1934.65 ; U5.20@2060.86,2302.68 2060.86,2240.33 ccw(c2114.69,2240.33) v1(2076.62,2202.26) ; U4.39@2101.59,1873.9 2101.59,1914.55 cw(c2129.99,1914.55) 2109.89,1934.62
  Bottom Layer w6: v1(1991.54,2113.09) 2077.64,2113.09 ccw(c2077.64,2133.78) 2092.27,2119.15 ccw(c2085.73,2125.7) 2094.99,2125.7 2094.99,2157.93 ccw(c2032.29,2157.93) v1(2076.62,2202.26)
RSET: R14.1 U5.48 | length 194.7
  Top Layer w8: R14.1@1791.7,2586.75 R14.1@1789.55,2586.75 ccw(c1826.16,2623.36) 1826.16,2571.58 1939.3,2571.58 cw(c1939.3,2561.55) 1946.4,2568.65 cw(c1936.21,2558.45) 1950.62,2558.45 U5.48@1950.62,2538.9
RST#: C33.1 JP1.8 P5.2 R36.2 R41.7 R52.1 S1.1 U4.30 | length 5538.4
  Top Layer w6: U4.30@2196.78,1780.11 2277.48,1780.11 ccw(c2277.48,1812.38) 2300.29,1789.56 cw(c2350.58,1739.27) 2350.58,1810.4 2534.8,1810.4 ccw(c2534.8,1843.47) 2539.26,1810.7 ccw(c2534.8,1843.47) 2558.18,1820.08 R36.2@2617.23,1879.13 2617.23,1937.81 ccw(c2614.75,1937.81) v2(2616.5,1939.56) ; P5.2@2685.09,83.11 2718.38,116.4 cw(c2789.1,45.69) 2789.1,145.69 2971.69,145.69 cw(c2971.69,45.69) 3042.4,116.4 3097.62,61.19 ccw(c3168.33,131.9) 3168.33,31.9 3436.99,31.9 ccw(c3436.99,131.9) 3507.7,61.19 S1.1@3544.26,97.75 ; R52.1@3508.47,897.08 3584.77,820.78 ccw(c3612.66,848.67) JP1.8@3612.66,809.23 3489.88,686.45 ccw(c3560.59,615.74) 3460.59,615.74 3460.59,276.54 ccw(c3548.17,276.54) 3486.24,214.61 3487.37,213.48 ccw(c3558.08,284.19) 3558.08,184.19 C33.1@3567.1,184.19 3567.1,152.88 cw(c3489.13,152.88) S1.1@3544.26,97.75 ; S1.1@3544.26,97.75 ccw(c3489.13,152.88) S1.1@3544.26,97.75
  Bottom Layer w6: v2(2616.5,1939.56) 2989.48,2312.54 3032.43,2355.49 cw(c3103.14,2284.77) 3103.14,2384.77 3805.98,2384.77 cw(c3805.98,2309.93) 3858.9,2362.85 3859.65,2362.1 cw(c3788.94,2291.39) 3888.94,2291.39 3888.94,2234.14 3888.94,1137.8 cw(c3762.68,1137.8) 3851.96,1048.52 JP1.8@3612.66,809.23
  other v2: 2399.88,1811.81
RX_N: C31.2 FMI1.3 R24.2 | length 1199.5
  Top Layer w6.07: FMI1.3@1414.36,2905.51 cw(c1369.89,2905.51) 1369.89,2861.05 1368.23,2861.05 cw(c1368.33,2907.77) 1335.29,2874.73 cw(c1379.02,2918.47) 1317.17,2918.47 1317.17,3614.48 cw(c1387.03,3614.48) 1387.03,3684.34 1541.31,3684.34 cw(c1541.31,3678.28) 1545.6,3682.57 cw(c1541.31,3678.28) 1547.38,3678.28 1547.38,3678.01 ccw(c1554.09,3678.01) 1549.33,3673.27 C31.2@1552.22,3670.39
  Bottom Layer w6.07: R24.2@1351.81,2909.48 ccw(c1361.39,2919.06) 1361.39,2905.51 FMI1.3@1414.36,2905.51
RX_P: C30.2 FMI1.2 R23.2 | length 1233.8
  Top Layer w6.07: FMI1.2@1414.36,2805.51 ccw(c1369.89,2805.51) 1369.89,2849.98 1368.22,2849.98 cw(c1368.22,2907.51) 1327.54,2866.83 1326.36,2868.01 cw(c1375.25,2916.9) 1306.11,2916.9 1306.11,3614.51 cw(c1387,3614.51) 1387,3695.41 1541.5,3695.41 ccw(c1541.5,3701.48) 1545.79,3697.19 ccw(c1541.5,3701.48) 1547.57,3701.48 1547.57,3701.75 cw(c1554.28,3701.75) 1549.52,3706.48 C30.2@1552.41,3709.37
  Bottom Layer w6.07: R23.2@1351.81,2804.76 1412.56,2804.76 ccw(c1412.56,2807.31) FMI1.2@1414.36,2805.51
RXD: J3.3 U4.13 | length 1465.9
  Top Layer w6.07: U4.13@2101.59,1560.34 2101.59,1523.38 ccw(c2201.59,1523.38) 2130.88,1452.67 2470.32,1113.22 cw(c2399.61,1042.51) 2499.61,1042.51 2499.61,778.61 ; 2499.61,785.74 2499.61,778.61 ; J3.3@2785.09,367.45 2785.09,410.3 ccw(c2685.09,410.3) 2755.8,481.01 2528.9,707.9 cw(c2599.61,778.61) 2499.61,778.61
RXD3: J6.2 R87.1 | length 1565.2
  Bottom Layer w6: R87.1@2343.67,1963.28 2361.42,1963.28 ccw(c2361.42,2063.28) 2432.13,1992.57 3003.2,2563.64 cw(c3073.91,2492.93) 3073.91,2592.93 3458.03,2592.93 cw(c3458.03,2492.93) 3528.74,2563.64 J6.2@3613.66,2478.72
SCK: JP1.3 R21.2 | length 5042.1
  Bottom Layer w6: R21.2@1845.06,1957.02 ccw(c1829.09,1941.05) 1829.09,1963.64 1662.63,1963.64 ccw(c1662.63,1863.64) 1591.92,1934.35 1493.31,1835.73 cw(c1422.6,1906.44) 1422.6,1806.44 1105.55,1806.44 ccw(c1105.55,1759.64) 1058.74,1759.64 1058.74,1444.99 ccw(c1158.74,1444.99) 1088.03,1374.28 1321.14,1141.18 cw(c1250.43,1070.47) 1350.43,1070.47 1350.43,283.41 ccw(c1450.43,283.41) 1450.43,183.41 1523.26,183.41 3138.29,183.41 ccw(c3138.29,329.54) 3241.62,226.21 3546.44,531.03 cw(c3617.15,460.32) 3617.15,560.32 3637.22,560.32 ccw(c3637.22,624.38) 3682.52,579.08 JP1.3@3712.66,609.23
SCK1: U4.58 U8.6 | length 4839.8
  Top Layer w6.07: v2(1514.84,1769.42) cw(c1541.84,1742.42) 1541.84,1780.6 1787.66,1780.6 cw(c1787.66,1741.44) 1815.35,1769.13 ccw(c1864.88,1818.66) 1834.55,1755.52 ccw(c1864.88,1818.66) 1864.88,1748.62 U4.58@1880.41,1748.62 ; U8.6@3305.36,711.58 ccw(c3309.89,716.1) 3309.89,709.7 v2(3388.95,709.7)
  Bottom Layer w6.07: v2(1514.84,1769.42) 1137.63,1769.42 ccw(c1137.63,1725.12) 1093.33,1725.12 1093.33,1466.23 ccw(c1193.33,1466.23) 1122.62,1395.52 1350.48,1167.66 cw(c1279.77,1096.95) 1379.77,1096.95 1379.77,311.29 ccw(c1479.77,311.29) 1479.77,211.29 1544.5,211.29 3079.78,211.29 ccw(c3079.78,311.29) 3150.49,240.58 3361.11,451.2 ccw(c3290.4,521.91) 3390.4,521.91 3390.4,713.58 ccw(c3393.91,710.07) 3388.95,710.07 v2(3388.95,709.7)
SCS: JP1.1 R22.2 | length 5082.4
  Bottom Layer w6: R22.2@1845.64,1999.15 1661.55,1999.15 ccw(c1661.55,1933.81) 1656.28,1998.94 ccw(c1661.55,1933.81) 1615.35,1980.01 ccw(c1676.7,1901.04) 1605.99,1971.75 1484.71,1850.47 cw(c1414,1921.18) 1436.47,1823.74 cw(c1414,1921.18) 1414,1821.18 1097.13,1821.18 ccw(c1097.13,1765.11) 1041.05,1765.11 1041.05,1432.91 ccw(c1141.05,1432.91) 1070.34,1362.2 1305.42,1127.12 cw(c1234.71,1056.41) 1334.71,1056.41 1334.71,268.59 ccw(c1434.71,268.59) 1434.71,168.59 1508.57,168.59 3312.03,168.59 ccw(c3312.03,313.43) 3414.45,211.01 JP1.1@3712.66,509.23
SCS1#: U4.57 U8.1 | length 4673.3
  Top Layer w6.07: v2@1455.36,1727.73 cw(c1522.38,1727.73) 1474.99,1775.12 cw(c1520.1,1730.01) 1520.1,1793.81 1795.68,1793.81 cw(c1795.68,1787.74) 1798.03,1793.33 1818.01,1785.03 cw(c1815.71,1779.42) 1820,1783.71 ccw(c1866.77,1830.57) 1866.77,1764.37 U4.57@1880.41,1764.37 ; U8.1@3035.36,811.58 3125.6,811.58 cw(c3125.6,808.94) 3127.47,810.8 v2(3127.56,810.71)
  Bottom Layer w6.07: v2(1455.36,1731.09) 1160.92,1731.09 ccw(c1160.92,1696.98) 1126.81,1696.98 1126.81,1488.58 ccw(c1226.81,1488.58) 1156.1,1417.87 1381.1,1192.87 cw(c1310.38,1122.16) 1410.38,1122.16 1410.38,338.23 ccw(c1510.38,338.23) 1510.38,238.23 3012.35,238.23 ccw(c3012.35,338.23) 3083.06,267.52 3098.27,282.73 ccw(c3027.56,353.44) 3127.56,353.44 v2(3127.56,810.71)
SSRX_n: J5.5 U4.8 | length 985.6
  Top Layer w8.22: U4.8@2022.85,1560.34 2022.85,1541.7 cw(c2018.53,1541.7) 2021.58,1538.64 2021.58,1529.22 ccw(c2049.8,1529.22) 2029.85,1509.26 ; 2029.87,1509.24 cw(c1988.02,1467.44) 2047.17,1467.44 2047.17,1448.37 ccw(c2129.04,1448.37) 2071.15,1390.48 2076.91,1384.72 cw(c2037.49,1345.3) 2093.24,1345.3 2093.24,655.69 ccw(c2131.79,655.69) 2104.53,628.43 J5.5@2126,606.96
SSRX_p: J5.6 U4.7 | length 985.6
  Top Layer w8.22: U4.7@2007.1,1560.34 2007.1,1541.7 ccw(c2011.41,1541.7) 2008.36,1538.64 2008.36,1529.22 ccw(c2049.8,1529.22) 2020.5,1499.91 ; 2020.52,1499.89 cw(c1988.02,1467.44) 2033.95,1467.44 2033.95,1448.37 ccw(c2129.04,1448.37) 2061.8,1381.14 2067.56,1375.38 cw(c2037.49,1345.3) 2080.02,1345.3 2080.02,655.69 cw(c2041.46,655.69) 2068.73,628.43 J5.6@2047.26,606.96
SSTX_n: C71.1 U4.5 | length 134.3
  Top Layer w8.22: U4.5@1975.6,1560.34 1975.6,1541.7 cw(c1971.29,1541.7) 1974.34,1538.64 1974.34,1453.61 ccw(c2009.07,1453.61) C71.1@1984.51,1429.06
SSTX_p: C72.1 U4.4 | length 134.3
  Top Layer w8.22: C72.1@1951.01,1429.06 ccw(c1926.62,1453.45) 1961.12,1453.45 1961.12,1538.64 cw(c1964.17,1541.7) 1959.85,1541.7 U4.4@1959.85,1560.34
TCK: P5.4 U4.55 | length 4267.9
  Top Layer w6.07: v2(1410.11,1875) 1436.63,1848.48 ccw(c1507.34,1919.19) 1507.34,1819.19 ; 1552.79,1819.19 1507.34,1819.19 ; U4.55@1880.41,1795.86 1854.81,1795.86 cw(c1854.81,1821.25) 1836.86,1803.3 1832.05,1808.11 ccw(c1805.3,1781.36) 1805.3,1819.19 1507.34,1819.19
  Bottom Layer w6.07: v2(1410.11,1875) 1399.92,1875 ccw(c1399.92,1833.73) 1370.74,1862.91 cw(c1311.51,1922.14) 1311.51,1838.38 1070.6,1838.38 ccw(c1070.6,1792.91) 1038.45,1825.06 ccw(c1070.63,1792.88) 1025.12,1792.88 1025.12,1744.67 ccw(c1031.09,1743.57) 1025.02,1743.57 1025.02,1419.79 ccw(c1125.02,1419.79) 1054.31,1349.08 1291.19,1112.2 cw(c1220.48,1041.49) 1320.48,1041.49 1320.48,252.55 ccw(c1420.48,252.55) 1420.48,152.55 2821.8,152.55 cw(c2821.8,120.43) 2841.96,145.43 ; 2842.5,145.01 2842.08,145.43 2841.96,145.43 ; 2842.6,144.96 2842.95,144.96 2843.35,144.57 ; 2843.38,144.57 2843.44,144.51 2843.68,144.51 2844.5,143.69 ; 2844.54,143.66 2849.9,138.3 ; P5.4@2885.09,103.11 2849.9,138.3 ; 2841.96,145.43 cw(c2779.19,67.59) 2849.9,138.3
TIO: P5.3 U4.56 | length 4182.2
  Top Layer w6.07: v2(1299.17,1867.38) 1331,1835.55 ccw(c1401.71,1906.26) 1401.71,1806.26 ; 1421.27,1806.26 1401.71,1806.26 ; U4.56@1880.41,1780.11 1853.43,1780.11 cw(c1853.43,1804.05) 1836.5,1787.13 1832.64,1790.98 ccw(c1795.75,1754.1) 1795.75,1806.26 1401.71,1806.26
  Bottom Layer w6.07: v2(1299.17,1867.38) 1107.78,1867.38 ccw(c1107.78,1861.31) 1106.04,1867.13 1082.17,1867.13 ccw(c1082.17,1792.74) 1007.78,1792.74 1007.78,1407.73 ccw(c1107.78,1407.73) 1037.07,1337.02 1275.69,1098.4 cw(c1204.98,1027.69) 1304.98,1027.69 1304.98,238.45 ccw(c1404.98,238.45) 1376.5,142.59 ccw(c1404.98,238.45) 1404.98,138.45 2733.88,138.45 cw(c2733.88,100.15) 2760.96,127.23 P5.3@2785.09,103.11
TX_N: C29.2 FMI1.7 R7.1 R11.1 | length 1292.9
  Top Layer w6.07: FMI1.7@1414.36,3305.51 cw(c1458.82,3305.51) 1458.82,3349.98 1759,3349.98 cw(c1759,3249.98) 1829.71,3320.69 2031.91,3118.49 cw(c1961.2,3047.78) 2061.2,3047.78 2061.2,2755.86 cw(c2013.5,2755.86) C29.2@2047.23,2722.14
  Bottom Layer w6.07: R7.1@1338.98,3268.74 R11.1@1338.98,3335.66 1339.84,3334.8 ccw(c1410.55,3405.51) 1410.55,3305.51 FMI1.7@1414.36,3305.51
TX_P: C28.2 FMI1.8 R6.1 R8.1 | length 1303.8
  Top Layer w6.07: FMI1.8@1414.36,3405.51 ccw(c1458.82,3405.51) 1458.82,3361.05 1759.04,3361.05 cw(c1759.04,3250.08) 1837.5,3328.54 2039.85,3126.2 cw(c1961.6,3047.94) 2072.27,3047.94 2072.27,2755.86 ccw(c2119.96,2755.86) C28.2@2086.24,2722.14
  Bottom Layer w6.07: R6.1@1338.98,3469.48 R8.1@1338.98,3402.57 1411.42,3402.57 ccw(c1411.42,3405.51) FMI1.8@1414.36,3405.51
TXD: J3.2 U4.12 | length 1486.4
  Top Layer w6.07: U4.12@2085.84,1560.34 2085.84,1522.04 ccw(c2185.84,1522.04) 2115.13,1451.33 2440.39,1126.07 cw(c2369.68,1055.36) 2469.68,1055.36 2469.68,770.76 ; 2469.68,816.85 2469.68,770.76 ; J3.2@2685.09,351.05 J3.2@2685.09,367.45 2685.09,472.51 ccw(c2585.09,472.51) 2655.8,543.22 2498.97,700.05 cw(c2569.68,770.76) 2469.68,770.76
TXD3: J6.3 R86.1 | length 1526.5
  Bottom Layer w6: R86.1@2270.88,1908.43 R86.1@2271.88,1908.43 ; R86.1@2271.88,1910.43 2335.49,1910.43 ccw(c2335.49,2010.43) 2382.05,1921.93 ccw(c2335.49,2010.43) 2406.2,1939.72 2989.76,2523.28 cw(c3060.47,2452.57) 3060.47,2552.57 3398.39,2552.57 cw(c3398.39,2452.57) 3469.1,2523.28 J6.3@3513.66,2478.72
UD_n: J5.2 U4.2 | length 1913.1
  Top Layer w8.22: U4.2@1928.36,1560.34 1928.36,1541.7 cw(c1924.04,1541.7) 1927.09,1538.64 1927.09,1528.22 cw(c1901.28,1528.22) 1919.53,1509.97 1905.95,1496.39 ccw(c1976.66,1425.67) 1876.66,1425.67 1876.66,1288.61 cw(c1763.44,1288.61) 1843.5,1208.55 1590.72,955.76 ccw(c1661.43,885.05) 1561.43,885.05 1561.43,433.81 ccw(c1661.43,433.81) 1590.72,363.1 1600.01,353.8 ccw(c1652.94,406.73) 1652.94,331.88 1873.62,331.88 ccw(c1873.62,411.88) 1930.19,355.31 1942.92,368.04 ccw(c1891.13,419.83) 1964.37,419.83 1964.37,514.71 J5.2@1932.61,546.48
UD_p: J5.3 U4.1 | length 1955.1
  Top Layer w8.22: U4.1@1912.61,1560.34 1912.61,1541.7 ccw(c1916.93,1541.7) 1913.87,1538.64 1913.87,1528.22 cw(c1901.28,1528.22) 1910.18,1519.31 1896.6,1505.73 ccw(c1976.66,1425.68) 1863.44,1425.68 1863.44,1288.61 cw(c1763.44,1288.61) 1834.15,1217.9 1581.37,965.11 ccw(c1661.43,885.05) 1548.21,885.05 1548.21,433.81 ccw(c1661.43,433.81) 1581.37,353.75 1590.66,344.45 ccw(c1652.94,406.73) 1652.94,318.66 1873.62,318.66 ccw(c1873.62,411.88) 1939.54,345.96 1952.27,358.69 ccw(c1891.13,419.83) 1977.59,419.83 1977.59,514.71 cw(c1984.61,514.71) 1979.65,519.67 J5.3@2007.89,547.91
VDDREG: C17.2 C18.2 R10.2 U5.31 | length 1535.1
  Top Layer w6: U5.31@2155.35,2428.67 2219.98,2428.67 ccw(c2219.98,2481.02) 2257,2444 2332.04,2519.04 ccw(c2321.06,2530.02) C17.2@2336.58,2530.02
  Top Layer w20: C17.2@2336.58,2530.02 2336.58,2551.91 cw(c2359.27,2551.91) 2343.23,2567.96 cw(c2395.05,2516.13) 2395.05,2589.42 2577.02,2589.42 ccw(c2577.02,2689.42) 2647.73,2618.71 2677.59,2648.57 ccw(c2606.88,2719.29) 2706.88,2719.29 2706.88,2893.73 cw(c2806.88,2893.73) 2736.17,2964.44 2780.51,3008.77 ccw(c2709.79,3079.48) 2809.79,3079.48 2809.79,3217.78 ccw(c2753.62,3217.78) 2793.34,3257.5 ccw(c2745.62,3209.79) 2745.62,3277.27 2706.6,3277.27 ccw(c2706.6,3239.78) 2680.09,3266.29 ccw(c2710.18,3236.19) 2667.62,3236.19 C18.2@2667.62,3208.28 R10.2@2594.58,3208.28
VIO: C23.1 C32.1 C51.2 C61.1 C62.1 C63.1 C64.1 P3.2 R74.1 R75.1 R84.2 U4.16 U4.42 U4.61 U7.AA3 U7.AA5 U7.K6 U7.W4 U7.Y4 | length 6315.5
  Top Layer w6: v3@1757.78,1724.81 1806.07,1724.81 cw(c1806.07,1706.71) 1818.87,1719.51 ccw(c1862.66,1763.3) 1862.66,1701.37 U4.61@1880.41,1701.37 ; U4.42@2054.34,1873.9 v2@2054.34,1937.87 ; U4.16@2148.83,1560.34 2148.83,1523.7 ccw(c2166.77,1523.7) 2154.09,1511.01 ; U7.AA3@3462.1,2858.63 ccw(c3496.25,2858.63) 3472.1,2834.48 cw(c3458.12,2820.5) 3472.14,2834.44 cw(c3448.59,2810.9) 3481.89,2810.9 v9@3481.89,2802.64 ; U7.W4@3481.78,2898 U7.Y4@3481.78,2878.31 U7.AA5@3501.47,2858.63 ccw(c3517.56,2858.63) 3506.18,2847.24 v5@3523.09,2830.34 ; U7.K6@3521.15,3075.16 3540.48,3055.83 v4(3570.78,3055.83)
  Top Layer w15: v3(3361.42,2953.27) ccw(c3396.99,2953.27) 3371.84,2928.12 3385.39,2914.57 cw(c3356.72,2885.9) 3397.26,2885.9 3397.26,2832.44 ccw(c3410.77,2832.44) 3401.22,2822.88 ccw(c3425.06,2846.72) 3425.06,2813.01 v3(3428.69,2813.01)
  Top Layer w30: P3.2@843.97,1697.92 864.03,1697.92 cw(c864.03,1597.92) 934.74,1668.63 936.64,1666.73 cw(c865.93,1596.02) 965.93,1596.02 R84.2@965.93,1445.02
  Layer 2 w20: 1728.01,1747.59 1752.52,1747.59 ccw(c1752.52,1800) 1789.58,1762.94 ; v3(1747.78,1727.81) cw(c1777.91,1697.69) 1756.39,1734.46 ccw(c1756.39,1745.81) 1764.42,1737.78 1764.89,1738.25 cw(c1777.91,1697.69) 1777.91,1740.29 1784.54,1740.29 cw(c1784.54,1674.13) 1809.01,1735.6 ; v3(2163.09,1500.01) 2127.31,1535.79 ccw(c2056.6,1465.08) 2056.6,1565.08 1921,1565.08 cw(c1921,1647.98) 1862.39,1589.36 cw(c1884.44,1611.41) 1853.25,1611.41 1853.25,1669.77 ccw(c1782.73,1669.77) 1832.6,1719.64 1831.32,1720.91 ccw(c1784.54,1674.13) 1809.01,1735.6 ; v3(3361.42,2953.27) 3361.42,2971 cw(c3420.85,2971) 3378.83,3013.03 cw(c3417.86,2973.99) 3417.86,3029.19 3510.43,3029.19 ccw(c3510.43,3110.59) 3567.98,3053.03 v4(3570.78,3055.83) ; v3(3428.69,2813.01) cw(c3404.34,2837.36) 3404.34,2802.92 v3(2934.8,2802.92) 2798.91,2802.92 ccw(c2798.91,2710.66) 2733.67,2775.9 ccw(c2791.49,2718.08) 2711.51,2735.08 ccw(c2791.49,2718.08) 2709.72,2718.08 2709.72,2670.44 2709.72,1951.97 cw(c2639.77,1951.97) 2639.77,1882.01 2228.6,1882.01 cw(c2228.6,1982.01) 2157.89,1911.3 2153.87,1915.32 ccw(c2083.16,1844.61) 2083.16,1944.61 v2(2057.59,1944.61) ccw(c2057.59,1906.37) 2030.55,1933.41 1989.74,1892.6 cw(c1950.35,1931.99) 1950.35,1876.29 1944.34,1876.29 ccw(c1944.34,1776.29) 1873.63,1847 1811.42,1784.78 ccw(c1842.82,1753.4) 1798.43,1753.85 ccw(c1838.03,1764.62) 1809.01,1735.6
  Layer 2 w30: P3.2@843.97,1697.92 938.84,1792.79 cw(c1009.55,1722.08) 1009.55,1822.08 1612.1,1822.08 cw(c1612.1,1722.08) 1682.81,1792.79 1728.01,1747.59
  Bottom Layer w15: v3(3361.42,2953.27) ccw(c3363.81,2955.66) 3363.81,2952.28 R74.1@3398.87,2952.28 ccw(c3421.61,2952.28) 3405.53,2936.2 3425.31,2916.42 cw(c3408.35,2899.46) C61.1@3432.34,2899.46
  Bottom Layer w20: v3(2934.8,2802.92) cw(c2936.61,2801.11) 2936.61,2803.67 R75.1@2989.6,2803.67
  Bottom Layer w25: v3(3428.69,2813.01) cw(c3428.69,2778.64) 3453,2802.94 C63.1@3454.09,2801.85 3524.91,2801.85 ccw(c3524.91,2803.57) 3526.13,2802.36 3526.13,2821.09 ccw(c3518.22,2821.09) v5(3523.81,2826.68) 3531.14,2834 cw(c3601.85,2763.29) 3601.85,2863.29 3628.57,2863.29 ccw(c3628.57,2932.77) 3677.71,2883.64 3679.2,2885.14 ccw(c3608.49,2955.85) 3708.49,2955.85 3708.49,3043.45 ccw(c3608.49,3043.45) 3679.2,3114.16 3677.24,3116.13 ccw(c3624.62,3063.51) 3624.62,3137.93 3597.13,3137.93 ccw(c3597.13,3119.47) 3584.08,3132.52 3580.65,3129.09 ccw(c3597.3,3112.44) 3573.76,3112.44 C64.1@3573.76,3090.21
  Bottom Layer w30: C32.1@1727.98,1780.45 cw(c1680.17,1732.64) 1747.78,1732.64 v3(1747.78,1727.81)
  other v9: 3483.89,2802.64
XTAL1: C57.2 R60.1 U5.46 X2.3 | length 486.5
  Top Layer w6: R60.1@1659.93,2643.05 cw(c1663.54,2646.66) 1658.43,2646.66 C57.2@1658.43,2711.06 1703.73,2711.06 cw(c1703.73,2661.55) X2.3@1738.73,2696.56 1778.26,2657.04 ccw(c1848.97,2727.75) 1848.97,2627.75 1934.08,2627.75 cw(c1934.08,2596.04) 1956.5,2618.46 1976.99,2597.97 cw(c1964.63,2585.6) 1977.88,2597.01 cw(c1964.63,2585.6) 1982.12,2585.6 U5.46@1982.12,2538.9
XTAL2: C59.2 U5.45 X2.1 | length 372.5
  Top Layer w6: C59.2@1826.58,2844.91 1826.58,2777.9 ccw(c1835.82,2777.9) X2.1@1829.29,2771.36 ccw(c1837.64,2771.36) 1831.73,2765.45 1972.8,2624.38 cw(c1912.3,2563.88) 1997.87,2563.88 U5.45@1997.87,2538.9
pads on no net: FMI1.10 FMI1.11 S3.0 S3.3 U2. U5.33 U6.0 U7. U7.A4 U7.A6 U7.A9 U7.A11 U7.AA1 U7.AA7 U7.AA8 U7.AA9 U7.AA10 U7.AA11 U7.AA12 U7.AA13 U7.AA14 U7.AE1 U7.AE14 U7.AG2 U7.AG13 U7.AH4 U7.AH6 U7.AH9 U7.AH11 U7.B2 U7.B13 U7.D1 U7.D14 U7.H7 U7.H8 U7.H9 U7.H10 U7.H11 U7.H12 U7.H13 U7.H14 U7.J1 U7.J7 U7.J8 U7.J9 U7.J10 U7.J11 U7.J12 U7.J13 U7.J14 U7.K5 U7.K7 U7.K8 U7.K9 U7.K10 U7.K11 U7.K12 U7.K13 U7.K14 U7.L1 U7.L2 U7.L4 U7.L12 U7.L13 U7.L14 U7.M1 U7.M2 U7.M3 U7.M5 U7.M8 U7.M9 U7.M10 U7.M12 U7.M13 U7.M14 U7.N1 U7.N2 U7.N3 U7.N10 U7.N12 U7.N13 U7.N14 U7.P1 U7.P2 U7.P3 U7.P10 U7.P12 U7.P13 U7.P14 U7.R1 U7.R2 U7.R3 U7.R12 U7.R13 U7.R14 U7.T1 U7.T2 U7.T3 U7.T5 U7.T12 U7.T13 U7.T14 U7.U1 U7.U2 U7.U3 U7.U10 U7.U12 U7.U13 U7.U14 U7.V1 U7.V2 U7.V3 U7.V12 U7.V13 U7.V14 U7.W1 U7.W2 U7.W3 U7.W7 U7.W8 U7.W9 U7.W10 U7.W11 U7.W12 U7.W13 U7.W14 U7.Y1 U7.Y3 U7.Y6 U7.Y7 U7.Y8 U7.Y9 U7.Y10 U7.Y11 U7.Y12 U7.Y13 U7.Y14

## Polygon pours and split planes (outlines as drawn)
GND on Top Layer "GND_L01_P000" (hatched Horizontal grid 8 track 8, remove dead copper, pour order 0): -24.84,3942.86 cw(c-71,3896.69) -5.71,3896.69 -5.71,-11.83 3952.68,-11.83 cw(c3952.68,-18.69) 3957.53,-13.84 3957.53,3943.06
GND on Layer 1 "GND_L02_P001" (hatched Horizontal grid 8 track 8, remove dead copper, pour order 1): -26.69,3956.56 -26.69,47.68 ccw(c55.3,47.68) -2.67,-10.29 cw(c20.51,-33.47) 20.51,-0.68 3959.37,-0.68 3959.37,3910.18 ccw(c3893.78,3910.18) 3940.16,3956.56
GND on Layer 2 "GND_L03_P002" (hatched Horizontal grid 8 track 8, remove dead copper, pour order 2): -25.16,3959.15 ccw(c-9.73,3943.72) -31.56,3943.72 -31.56,-16.73 3948.07,-16.73 ccw(c3948.07,5.09) 3963.5,-10.34 cw(c3994.37,20.52) 3950.72,20.52 3950.72,3959.15
GND on Bottom Layer "GND_L04_P003" (hatched Horizontal grid 8 track 8, remove dead copper, pour order 3): -20.72,-1.71 3913.51,-1.71 ccw(c3913.51,47.62) 3948.4,12.74 3956.83,21.17 ccw(c3886.12,91.88) 3986.12,91.88 3986.12,3987.55 23.84,3987.55 ccw(c23.84,3908.09) -32.35,3964.27

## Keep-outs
Keep-Out Layer:
  lines w8: 0,137.8 ccw(c137.8,137.8) 137.8,0 3799.21,0 ccw(c3799.21,137.8) 3937.01,137.8 3937.01,3799.21 ccw(c3799.21,3799.21) 3799.21,3937.01 137.79,3937.01 ccw(c137.79,3799.21) 0,3799.21 0,137.8

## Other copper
Top Layer:
  rectangle net GND: 2729.88,2890.17 2958.31,2906.17
  pour cut-out: 980.85,906.17 980.85,706.17 cw(c1000.17,686.85) 1000.17,714.17 1170.21,714.17 1170.21,906.17
  pour cut-out: 1944.15,1436.75 1991.15,1436.75 1991.15,1385.76 1944.15,1385.76
  pour cut-out: 2097.37,2729.44 2097.37,2679.2 2035.79,2679.2 2035.79,2729.64
  pour cut-out: 1544.94,3720.53 1595.18,3720.53 1595.18,3658.94 1544.74,3658.94
  pour cut-out: 2960.43,2894.98
  pour cut-out: 2958.31,2852.68 2958.31,2814.43 3020.9,2814.43 3020.9,2852.3
  pour cut-out: 2854.02,2762.17 2854.02,2643.36 2916.61,2643.36 2916.61,2764.61
  pour cut-out: 469.91,906.17 659.26,906.17 659.26,706.17 469.91,706.17
Layer 1:
  rectangle net GND: 1937.86,2316.87 2147.87,2526.88
  rectangle net GND: 1912.41,1583.51 2196.17,1847.73
  pour cut-out: 2103.23,2734.57 2103.23,2674.41 2032.82,2674.41 2033.23,2734.41
  pour cut-out: 1539.97,3726.36 1600.14,3726.36 1600.14,3655.95 1540.14,3656.36
  pour cut-out: 1362.96,1539.16 1460.96,1539.16 1460.96,1635.16 1362.96,1635.16
Layer 2:
  rectangle net GND: 1923.95,1606.62 2177.12,1828.86
  rectangle net GND: 1947.26,2335.9 2138.01,2510.51
Bottom Layer:
  rectangle net GND: 1957.53,2344.55 2125.65,2505.83
  rectangle net GND: 1923.66,1593.26 2151.61,1830
  pour cut-out: 2307.74,2743.5 2510.13,2743.5 2510.13,2554.15 2307.74,2554.15
Multi-Layer:
  pour cut-out: 55.98,1599.86 55.98,1304.8 311.61,1304.8 311.61,1599.37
